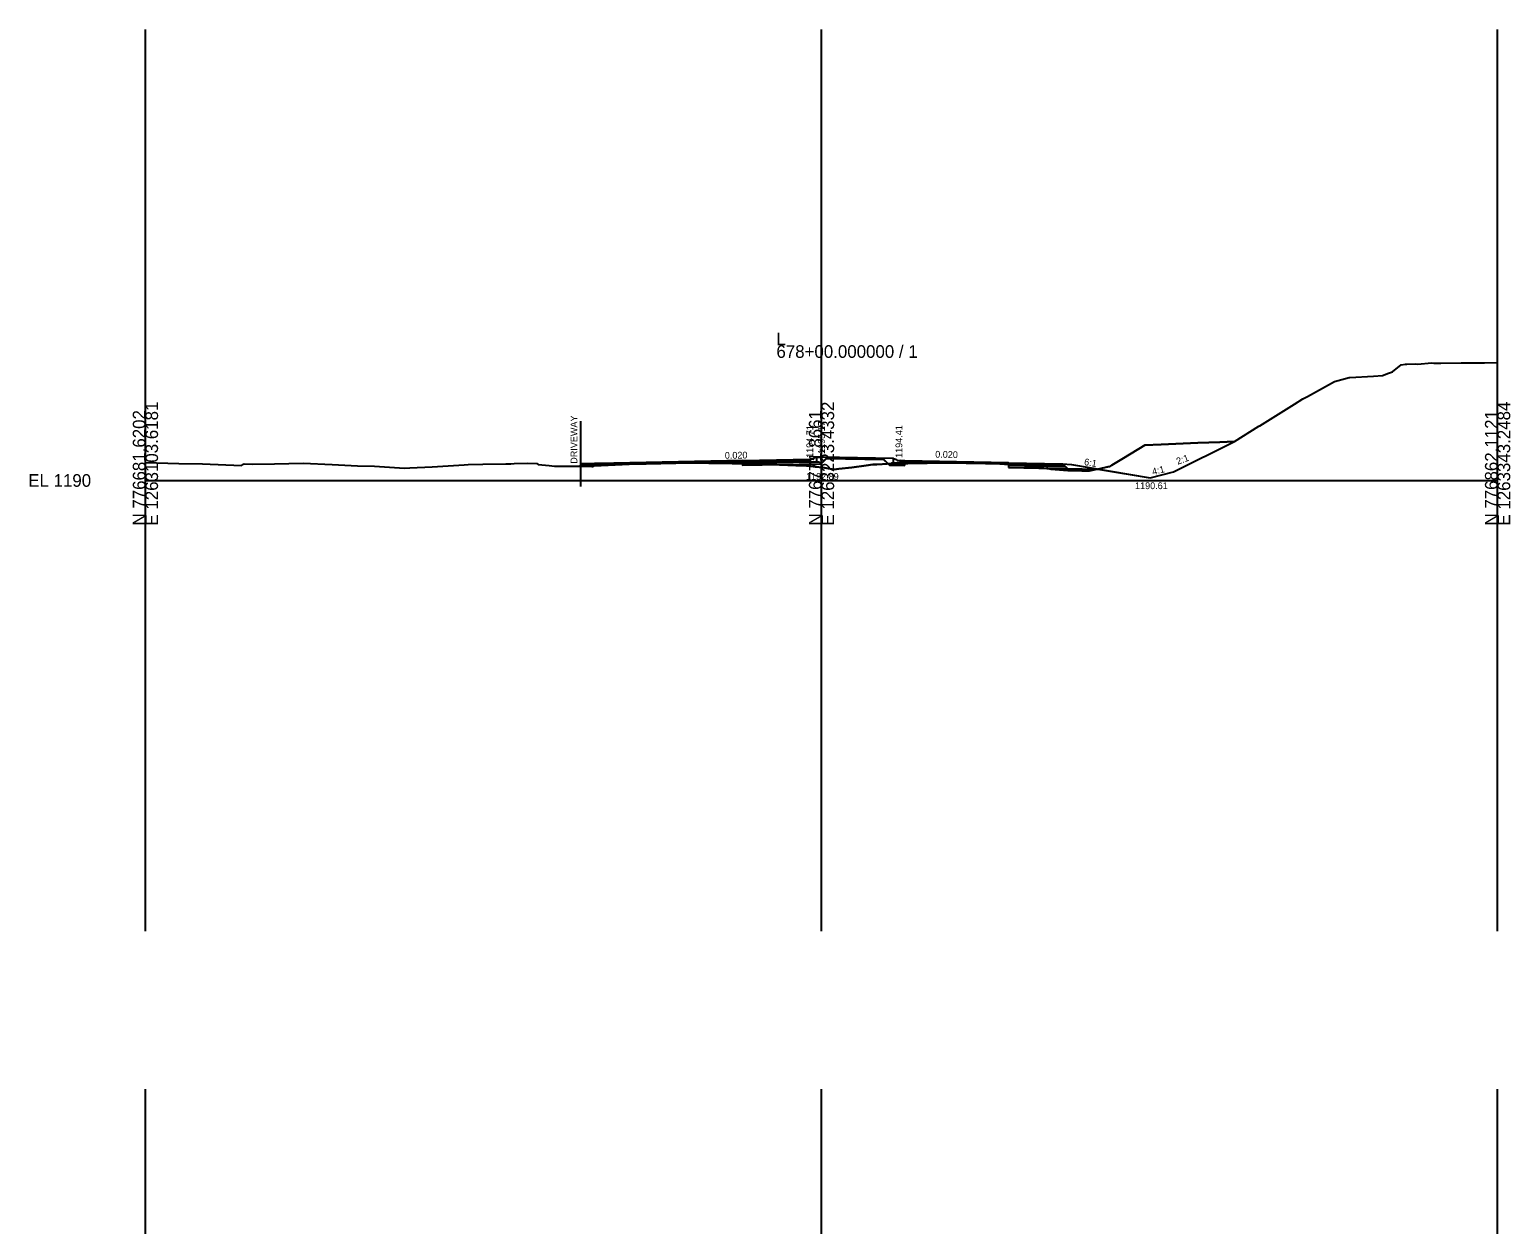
# Model space of a CAD drawing. Extents: x -41 to 1262860, y -100 to 777489.
# Drawn here: x 474.3 to 802.8, y 2220 to 2485 of the extents above; entities that cross this region are included whole.
import ezdxf

# ---------------------------------------------------------------- set-up
doc = ezdxf.new("R2010")
doc.units = 0
for name, color, linetype in [('Exist Cross Section Cell', 7, 'Continuous'), ('Exist XS Center Line Elevation Label', 7, 'Continuous'), ('Exist XS Ground Line', 7, 'Continuous'), ('Prop CMT Pvmt Course 1', 7, 'Continuous'), ('Prop CMT Pvmt Surface', 7, 'Continuous'), ('Prop CMT Shear Line', 7, 'Continuous'), ('Prop CMT Shld Paved Course 1', 7, 'Continuous'), ('Prop CMT Shld Paved Course 2', 7, 'Continuous'), ('Prop CMT Shld Paved Course 4', 7, 'Continuous'), ('Prop CMT Subgrade Earthwork', 7, 'Continuous'), ('Prop Conc Curb and Gutter', 7, 'Continuous'), ('Prop Conc Island Cover', 7, 'Continuous'), ('Prop XS Ditch Standard Text', 7, 'Continuous'), ('Prop XS Earthwork Shape', 7, 'Continuous'), ('Prop XS Elevation Labels', 7, 'Continuous'), ('Prop XS Exc Vertical Line 1', 7, 'Continuous'), ('Prop XS Exc Vertical Line 2', 7, 'Continuous'), ('Prop XS Exc Vertical Line 3', 7, 'Continuous'), ('Prop XS Finish Grade', 7, 'Continuous'), ('Prop XS Hydro Elevations', 7, 'Continuous'), ('Prop XS SE Text', 7, 'Continuous'), ('Prop XS Side Slope Text', 7, 'Continuous'), ('Scratch_Level_4', 7, 'Continuous'), ('Scratch_Level_6', 7, 'Continuous')]:
    doc.layers.add(name, color=color, linetype=linetype)

msp = doc.modelspace()

# ---------------------------------------------------------------- linework, layer by layer
at = {"layer": 'Exist Cross Section Cell'}
for p, q in [((650, 2385), (650, 2415)), ((500, 2385), (650, 2385)), ((650, 2385), (800, 2385))]:
    msp.add_line(p, q, dxfattribs=at)
at = {"layer": 'Exist XS Ground Line'}
msp.add_lwpolyline([(500, 2388.95), (507.41, 2388.78), (512.64, 2388.67), (521.33, 2388.33), (521.79, 2388.6), (521.9, 2388.66), (523.79, 2388.64), (528.61, 2388.71), (535.03, 2388.83), (541.44, 2388.55), (547.08, 2388.27), (550.79, 2388.19), (557.49, 2387.74), (558.63, 2387.78), (563.64, 2388.03), (570.71, 2388.46), (571.63, 2388.52), (574.83, 2388.59), (579.93, 2388.68), (581.09, 2388.7), (581.79, 2388.75), (584.88, 2388.87), (586.81, 2388.73), (587.15, 2388.55), (589.58, 2388.29), (590.74, 2388.16), (591.98, 2388.17), (595.39, 2388.17), (597.44, 2388.19), (599.07, 2388.08), (599.32, 2388.13), (599.53, 2388.23), (607.32, 2388.61), (611.12, 2388.83), (620.91, 2388.89), (623.01, 2388.91), (625.03, 2388.87), (635.26, 2388.72), (644.3, 2388.33), (646.68, 2388.24), (647.36, 2388.21), (647.73, 2388.2), (648.62, 2388.06), (650.29, 2387.85), (651.47, 2387.67), (652.83, 2387.43), (653.87, 2387.6), (656.7, 2387.88), (659.92, 2388.29), (661.38, 2388.51), (662.31, 2388.56), (665.73, 2388.73), (668.45, 2388.78), (677.84, 2388.92), (686.37, 2388.77), (689.55, 2388.69), (690.57, 2388.62), (693.54, 2388.41), (696.41, 2388.13), (700.58, 2387.55), (700.88, 2387.51), (704.62, 2387.24), (707.73, 2387.16), (709.47, 2387.14), (713.56, 2388.02), (713.95, 2388.12), (714.4, 2388.36), (716.97, 2389.94), (721.74, 2392.82), (725.33, 2392.97), (733.53, 2393.37), (738.34, 2393.51), (741.63, 2393.68), (747.05, 2397.02), (747.25, 2397.12), (754.93, 2401.91), (756.81, 2403.13), (757.8, 2403.63), (763.82, 2406.97), (767.04, 2407.82), (767.17, 2407.85), (767.21, 2407.86), (772.47, 2408.16), (774.5, 2408.26), (775.8, 2408.82), (776.66, 2409.09), (778.61, 2410.67), (778.62, 2410.67), (778.62, 2410.68), (779.58, 2410.83), (779.87, 2410.83), (781.71, 2410.87), (782.26, 2410.79), (785.42, 2411.09), (785.82, 2411.03), (787.4, 2411.03), (791.89, 2411.06), (793.15, 2411.09), (797.07, 2411.12), (800, 2411.16)], dxfattribs=at)
at = {"layer": 'Prop CMT Pvmt Course 1'}
for p, q in [((632.5, 2389.15), (647.46, 2389.45)), ((647.46, 2389.45), (647.46, 2389.7)), ((667.5, 2389.4), (667.5, 2389.15)), ((668.5, 2389.13), (667.5, 2389.15))]:
    msp.add_line(p, q, dxfattribs=at)
for points in [[(596.5, 2388.68), (596.5, 2388.43), (596.5, 2388.43), (599.64, 2388.49), (599.64, 2388.49), (599.77, 2388.5), (599.77, 2388.5), (599.92, 2388.5), (599.92, 2388.5), (600.06, 2388.5), (600.06, 2388.5), (600.19, 2388.5), (600.19, 2388.5), (600.27, 2388.51), (600.27, 2388.51), (628.97, 2389.08), (628.97, 2389.08), (632.5, 2389.15), (632.5, 2389.4), (632.5, 2389.4), (628.97, 2389.33), (628.97, 2389.33), (600.27, 2388.76), (600.27, 2388.76), (600.19, 2388.75), (600.19, 2388.75), (600.06, 2388.75), (600.06, 2388.75), (599.92, 2388.75), (599.92, 2388.75), (599.77, 2388.75), (599.77, 2388.75), (599.64, 2388.74), (599.64, 2388.74), (596.5, 2388.68), (596.5, 2388.68), (596.5, 2388.68)], [(691.5, 2388.92), (691.5, 2388.92), (668.5, 2389.38), (668.5, 2389.38), (668.5, 2389.38), (668.5, 2389.38), (668.5, 2389.38), (668.5, 2389.13), (668.5, 2389.13), (668.5, 2389.13), (668.5, 2389.13), (691.5, 2388.67), (691.5, 2388.92)]]:
    msp.add_lwpolyline(points, dxfattribs=at)
at = {"layer": 'Prop CMT Pvmt Surface'}
for p, q in [((596.5, 2388.68), (632.5, 2389.4)), ((632.5, 2389.4), (647.46, 2389.7)), ((668.5, 2389.38), (667.5, 2389.4)), ((668.5, 2389.38), (691.5, 2388.92)), ((691.5, 2388.92), (703.5, 2388.68))]:
    msp.add_line(p, q, dxfattribs=at)
at = {"layer": 'Prop CMT Shear Line'}
msp.add_line((596.5, 2398.12), (596.5, 2383.68), dxfattribs=at)
at = {"layer": 'Prop CMT Shld Paved Course 1'}
for p, q in [((691.5, 2388.92), (691.5, 2388.92)), ((691.5, 2388.92), (691.5, 2388.92)), ((691.5, 2388.92), (691.5, 2388.67)), ((691.5, 2388.67), (691.5, 2388.67)), ((691.5, 2388.67), (703.76, 2388.43)), ((695.5, 2388.84), (695.5, 2388.84)), ((703.76, 2388.43), (703.5, 2388.68))]:
    msp.add_line(p, q, dxfattribs=at)
at = {"layer": 'Prop CMT Shld Paved Course 2'}
for p, q in [((596.5, 2388.43), (597.44, 2388.45)), ((597.44, 2388.45), (599.07, 2388.48)), ((597.44, 2388.45), (597.44, 2388.45)), ((597.44, 2388.45), (597.44, 2388.45)), ((599.07, 2388.48), (599.32, 2388.49)), ((599.07, 2388.48), (599.07, 2388.48)), ((599.32, 2388.49), (599.32, 2388.49)), ((599.32, 2388.49), (599.53, 2388.49)), ((599.53, 2388.49), (599.53, 2388.49)), ((599.53, 2388.49), (599.53, 2388.49)), ((599.53, 2388.49), (599.53, 2388.49)), ((599.53, 2388.49), (599.64, 2388.49)), ((599.64, 2388.49), (599.77, 2388.5)), ((599.77, 2388.5), (599.77, 2388.5)), ((599.77, 2388.5), (599.92, 2388.5)), ((599.92, 2388.5), (599.92, 2388.5)), ((599.92, 2388.5), (600.06, 2388.5)), ((600.06, 2388.5), (600.06, 2388.5)), ((600.06, 2388.5), (600.19, 2388.5)), ((600.19, 2388.5), (600.27, 2388.51)), ((600.19, 2388.5), (600.19, 2388.5)), ((600.27, 2388.51), (607.32, 2388.65)), ((607.32, 2388.61), (600.27, 2388.27)), ((600.27, 2388.51), (600.27, 2388.51)), ((607.32, 2388.65), (611.12, 2388.72)), ((608.24, 2388.67), (607.32, 2388.61)), ((607.32, 2388.65), (607.32, 2388.65)), ((607.32, 2388.65), (607.32, 2388.65)), ((607.32, 2388.61), (607.32, 2388.61)), ((607.32, 2388.61), (607.32, 2388.61)), ((611.12, 2388.72), (608.24, 2388.67)), ((611.12, 2388.72), (620.91, 2388.92)), ((618.71, 2388.88), (611.12, 2388.72)), ((611.12, 2388.72), (611.12, 2388.72)), ((611.12, 2388.72), (611.12, 2388.72)), ((611.12, 2388.72), (611.12, 2388.72)), ((611.12, 2388.72), (611.12, 2388.72)), ((611.12, 2388.72), (611.12, 2388.72)), ((620.91, 2388.89), (618.71, 2388.88)), ((618.71, 2388.88), (618.71, 2388.88)), ((618.71, 2388.88), (618.71, 2388.88)), ((620.91, 2388.92), (623.01, 2388.96)), ((620.91, 2388.92), (620.91, 2388.92)), ((620.91, 2388.92), (620.91, 2388.92)), ((623.01, 2388.91), (620.91, 2388.89)), ((620.91, 2388.89), (620.91, 2388.89)), ((620.91, 2388.89), (620.91, 2388.89)), ((623.01, 2388.96), (625.03, 2389)), ((623.01, 2388.96), (623.01, 2388.96)), ((625.03, 2388.87), (623.01, 2388.91)), ((623.01, 2388.91), (623.01, 2388.91)), ((625.03, 2389), (628.97, 2389.08)), ((625.03, 2389), (625.03, 2389)), ((628.97, 2388.81), (625.03, 2388.87)), ((625.03, 2388.87), (625.03, 2388.87)), ((628.97, 2389.08), (632.5, 2389.15)), ((628.97, 2389.08), (628.97, 2389.08)), ((630.88, 2388.79), (628.97, 2388.81)), ((632.5, 2388.82), (630.88, 2388.79)), ((630.88, 2388.79), (630.88, 2388.79)), ((630.88, 2388.79), (630.88, 2388.79)), ((630.88, 2388.79), (630.88, 2388.79)), ((632.5, 2389.15), (632.5, 2389.15)), ((632.5, 2389.15), (632.5, 2389.15)), ((632.5, 2389.15), (632.5, 2388.82)), ((632.5, 2388.82), (647.46, 2389.12)), ((647.46, 2389.45), (647.46, 2389.12)), ((647.46, 2389.12), (647.46, 2389.12)), ((667.5, 2388.82), (667.5, 2389.15)), ((668.5, 2388.8), (667.5, 2388.82)), ((677.84, 2388.94), (668.5, 2389.13)), ((668.5, 2389.13), (668.5, 2389.13)), ((668.5, 2389.13), (668.5, 2389.13)), ((668.5, 2389.13), (668.5, 2389.13)), ((668.5, 2389.13), (668.5, 2389.13)), ((668.5, 2389.13), (668.5, 2389.13)), ((668.5, 2389.13), (668.5, 2388.8)), ((668.5, 2388.8), (668.5, 2388.8)), ((668.5, 2388.8), (668.5, 2388.8)), ((668.5, 2388.8), (668.5, 2388.8)), ((668.5, 2388.8), (669.12, 2388.79)), ((669.12, 2388.79), (677.84, 2388.92)), ((669.12, 2388.79), (669.12, 2388.79)), ((686.37, 2388.77), (677.84, 2388.94)), ((677.84, 2388.94), (677.84, 2388.94)), ((677.84, 2388.94), (677.84, 2388.94)), ((677.84, 2388.92), (677.84, 2388.92)), ((677.84, 2388.92), (677.84, 2388.92)), ((677.84, 2388.92), (686.37, 2388.77)), ((689.55, 2388.71), (686.37, 2388.77)), ((686.37, 2388.77), (686.37, 2388.77)), ((686.37, 2388.77), (686.37, 2388.77)), ((686.37, 2388.77), (689.55, 2388.69)), ((690.57, 2388.69), (689.55, 2388.71)), ((689.55, 2388.69), (690.57, 2388.62)), ((691.5, 2388.67), (690.57, 2388.69)), ((690.57, 2388.69), (690.57, 2388.69)), ((690.57, 2388.62), (690.57, 2388.62)), ((690.57, 2388.62), (691.5, 2388.56)), ((691.5, 2388.67), (691.5, 2388.67)), ((691.5, 2388.67), (691.5, 2388.67)), ((691.5, 2388.67), (691.5, 2388.34)), ((691.5, 2388.56), (691.5, 2388.67)), ((691.5, 2388.67), (691.5, 2388.67)), ((695.76, 2388.59), (695.76, 2388.59)), ((596.5, 2388.18), (596.5, 2388.43)), ((596.5, 2388.43), (596.5, 2388.43)), ((597.44, 2388.19), (596.5, 2388.18)), ((598.25, 2388.13), (597.44, 2388.19)), ((597.44, 2388.19), (597.44, 2388.19)), ((597.44, 2388.19), (597.44, 2388.19)), ((599.07, 2388.15), (598.25, 2388.13)), ((598.25, 2388.13), (598.25, 2388.13)), ((599.32, 2388.15), (599.07, 2388.15)), ((599.07, 2388.15), (599.07, 2388.15)), ((599.07, 2388.15), (599.07, 2388.15)), ((599.38, 2388.16), (599.32, 2388.15)), ((599.32, 2388.15), (599.32, 2388.15)), ((599.53, 2388.23), (599.38, 2388.16)), ((599.38, 2388.16), (599.38, 2388.16)), ((599.64, 2388.24), (599.53, 2388.23)), ((599.53, 2388.23), (599.53, 2388.23)), ((599.53, 2388.23), (599.53, 2388.23)), ((599.53, 2388.23), (599.53, 2388.23)), ((599.53, 2388.23), (599.53, 2388.23)), ((599.77, 2388.24), (599.64, 2388.24)), ((599.92, 2388.25), (599.77, 2388.24)), ((599.77, 2388.24), (599.77, 2388.24)), ((600.06, 2388.26), (599.92, 2388.25)), ((599.92, 2388.25), (599.92, 2388.25)), ((600.19, 2388.26), (600.06, 2388.26)), ((600.06, 2388.26), (600.06, 2388.26)), ((600.27, 2388.27), (600.19, 2388.26)), ((600.19, 2388.26), (600.19, 2388.26)), ((600.27, 2388.27), (600.27, 2388.27)), ((691.5, 2388.34), (691.5, 2388.34)), ((691.5, 2388.34), (704.1, 2388.09)), ((704.1, 2388.09), (703.76, 2388.43))]:
    msp.add_line(p, q, dxfattribs=at)
at = {"layer": 'Prop CMT Shld Paved Course 4'}
for p, q in [((630.88, 2388.79), (632.5, 2388.76)), ((632.5, 2388.82), (632.5, 2388.36)), ((632.5, 2388.36), (649.91, 2388.71)), ((647.46, 2389.12), (649.46, 2389.16)), ((649.46, 2389.16), (649.91, 2388.71)), ((665.5, 2388.86), (665.05, 2388.41)), ((667.5, 2388.82), (665.5, 2388.86)), ((668.5, 2388.34), (668.5, 2388.8)), ((669.12, 2388.79), (668.5, 2388.78)), ((599.07, 2388.08), (598.25, 2388.13)), ((599.32, 2388.13), (599.07, 2388.08)), ((599.38, 2388.16), (599.32, 2388.13)), ((668.5, 2388.34), (665.05, 2388.41)), ((691.5, 2388.34), (691.5, 2388.34)), ((691.5, 2388.34), (691.5, 2388.34)), ((691.5, 2388.34), (691.5, 2387.88)), ((691.5, 2387.88), (704.56, 2387.62)), ((696.1, 2388.25), (696.1, 2388.25)), ((696.6, 2388.24), (696.6, 2388.24)), ((704.56, 2387.62), (704.1, 2388.09))]:
    msp.add_line(p, q, dxfattribs=at)
at = {"layer": 'Prop CMT Subgrade Earthwork'}
for p, q in [((632.5, 2388.76), (632.5, 2388.36)), ((632.5, 2388.36), (649.91, 2388.71)), ((649.91, 2388.71), (651.35, 2390.14)), ((665.05, 2388.41), (663.56, 2389.9)), ((668.5, 2388.34), (668.5, 2388.78)), ((691.5, 2388.56), (691.5, 2387.88)), ((665.05, 2388.41), (668.5, 2388.34)), ((691.5, 2387.88), (711.78, 2387.47))]:
    msp.add_line(p, q, dxfattribs=at)
at = {"layer": 'Prop Conc Curb and Gutter'}
for p, q in [((648.15, 2389.71), (647.46, 2389.7)), ((647.46, 2389.7), (647.46, 2389.12)), ((647.46, 2389.12), (648.96, 2389.15)), ((648.21, 2389.79), (648.21, 2389.78)), ((648.96, 2390.15), (648.31, 2389.93)), ((648.96, 2389.15), (648.96, 2390.15)), ((648.96, 2389.15), (648.96, 2389.15)), ((666, 2389.85), (666.65, 2389.63)), ((666, 2388.85), (666, 2389.85)), ((667.5, 2388.82), (666, 2388.85)), ((666.75, 2389.49), (666.75, 2389.48)), ((666.81, 2389.41), (667.5, 2389.4)), ((667.5, 2388.82), (667.5, 2389.4))]:
    msp.add_line(p, q, dxfattribs=at)
for centre, radius, start, end in [((648.15, 2389.78), 0.0625, 271.1458, 360), ((648.36, 2389.79), 0.146, 108.435, 180), ((666.6, 2389.49), 0.146, 0, 71.565), ((666.81, 2389.48), 0.0625, 180, 268.8542)]:
    msp.add_arc(centre, radius, start, end, dxfattribs=at)
at = {"layer": 'Prop Conc Island Cover'}
for p, q in [((648.96, 2390.15), (650, 2390.17)), ((648.96, 2389.88), (648.96, 2389.88)), ((666, 2389.85), (650, 2390.17))]:
    msp.add_line(p, q, dxfattribs=at)
at = {"layer": 'Prop XS Earthwork Shape'}
for points in [[(722.94, 2385.61), (728.06, 2386.89), (741.63, 2393.68), (738.34, 2393.51), (733.53, 2393.37), (725.33, 2392.97), (721.74, 2392.82), (716.97, 2389.94), (714.4, 2388.36), (713.95, 2388.12), (713.56, 2388.02), (711.36, 2387.54), (711.78, 2387.47)], [(632.5, 2388.76), (632.5, 2388.36), (640.09, 2388.51), (635.26, 2388.72)], [(649.91, 2388.71), (651.1, 2389.9), (663.82, 2389.64), (664.78, 2388.68), (662.31, 2388.56), (661.38, 2388.51), (659.92, 2388.29), (656.7, 2387.88), (653.87, 2387.6), (652.83, 2387.43), (651.47, 2387.67), (650.29, 2387.85), (648.62, 2388.06), (647.73, 2388.2), (647.36, 2388.21), (646.68, 2388.24), (644.3, 2388.33), (640.09, 2388.51)], [(668.5, 2388.34), (668.5, 2388.78), (668.45, 2388.78), (665.73, 2388.73), (664.78, 2388.68), (665.05, 2388.41)], [(691.5, 2387.88), (699.33, 2387.72), (696.41, 2388.13), (693.54, 2388.41), (691.5, 2388.56)], [(704.56, 2387.62), (711.1, 2387.49), (709.47, 2387.14), (707.73, 2387.16), (704.62, 2387.24), (700.88, 2387.51), (700.58, 2387.55), (699.33, 2387.72)], [(711.1, 2387.49), (711.36, 2387.54), (711.78, 2387.47)]]:
    msp.add_lwpolyline(points, close=True, dxfattribs=at)
at = {"layer": 'Prop XS Exc Vertical Line 1'}
for p, q in [((500, 2285), (500, 2485)), ((500, 2050), (500, 2250))]:
    msp.add_line(p, q, dxfattribs=at)
at = {"layer": 'Prop XS Exc Vertical Line 2'}
for p, q in [((650, 2285), (650, 2485)), ((650, 2050), (650, 2250))]:
    msp.add_line(p, q, dxfattribs=at)
at = {"layer": 'Prop XS Exc Vertical Line 3'}
for p, q in [((800, 2285), (800, 2485)), ((800, 2050), (800, 2250))]:
    msp.add_line(p, q, dxfattribs=at)
at = {"layer": 'Prop XS Finish Grade'}
for p, q in [((728.06, 2386.89), (741.63, 2393.68)), ((703.5, 2388.68), (705.5, 2388.52)), ((703.5, 2388.68), (704.56, 2387.62)), ((705.5, 2388.52), (722.94, 2385.61)), ((722.94, 2385.61), (728.06, 2386.89))]:
    msp.add_line(p, q, dxfattribs=at)
at = {"layer": 'Scratch_Level_4'}
for p, q in [((800, 2285), (800, 2485)), ((800, 2050), (800, 2250))]:
    msp.add_line(p, q, dxfattribs=at)
at = {"layer": 'Scratch_Level_6'}
for p, q in [((500, 2285), (500, 2485)), ((500, 2050), (500, 2250))]:
    msp.add_line(p, q, dxfattribs=at)

# ---------------------------------------------------------------- texts
at = {"layer": 'Exist Cross Section Cell'}
for s, p in [('678+00.000000 / 1', (640, 2412.2)), ('L', (640, 2415)), ('EL 1190', (474, 2383.6))]:
    msp.add_text(s, height=2.8, dxfattribs=at).set_placement(p)
for s, p in [('E 1263103.6181', (502.8, 2375)), ('E 1263223.4332', (652.8, 2375)), ('E 1263343.2484', (802.8, 2375)), ('N 776681.6202', (500, 2375)), ('N 776771.8661', (650, 2375)), ('N 776862.1121', (800, 2375))]:
    msp.add_text(s, height=2.8, rotation=90, dxfattribs=at).set_placement(p)
at = {"layer": 'Exist XS Center Line Elevation Label'}
msp.add_text('1192.89', height=1.5, dxfattribs=at).set_placement((646.57, 2385.14))
at = {"layer": 'Prop XS Ditch Standard Text'}
msp.add_text('1190.61', height=1.5, dxfattribs=at).set_placement((719.57, 2383.08))
at = {"layer": 'Prop XS Elevation Labels'}
for s, p in [('1194.71', (648.16, 2390.01)), ('1194.41', (667.92, 2390.01))]:
    msp.add_text(s, height=1.5, rotation=90, dxfattribs=at).set_placement(p)
at = {"layer": 'Prop XS Hydro Elevations'}
for s, p in [('DRIVEWAY', (595.82, 2388.71)), ('1195.17', (650.75, 2390.89))]:
    msp.add_text(s, height=1.5, rotation=90, dxfattribs=at).set_placement(p)
at = {"layer": 'Prop XS SE Text'}
for rotation, p in [(1.1458, (628.56, 2389.79)), (358.8542, (675.22, 2390.07))]:
    msp.add_text('0.020', height=1.5, rotation=rotation, dxfattribs=at).set_placement(p)
at = {"layer": 'Prop XS Side Slope Text'}
for s, rotation, p in [('6:1', 350.5377, (708.19, 2388.43)), ('2:1', 20.1493, (729.04, 2388.48)), ('4:1', 14.0362, (723.54, 2386.18))]:
    msp.add_text(s, height=1.5, rotation=rotation, dxfattribs=at).set_placement(p)

doc.saveas('drawing.dxf')
